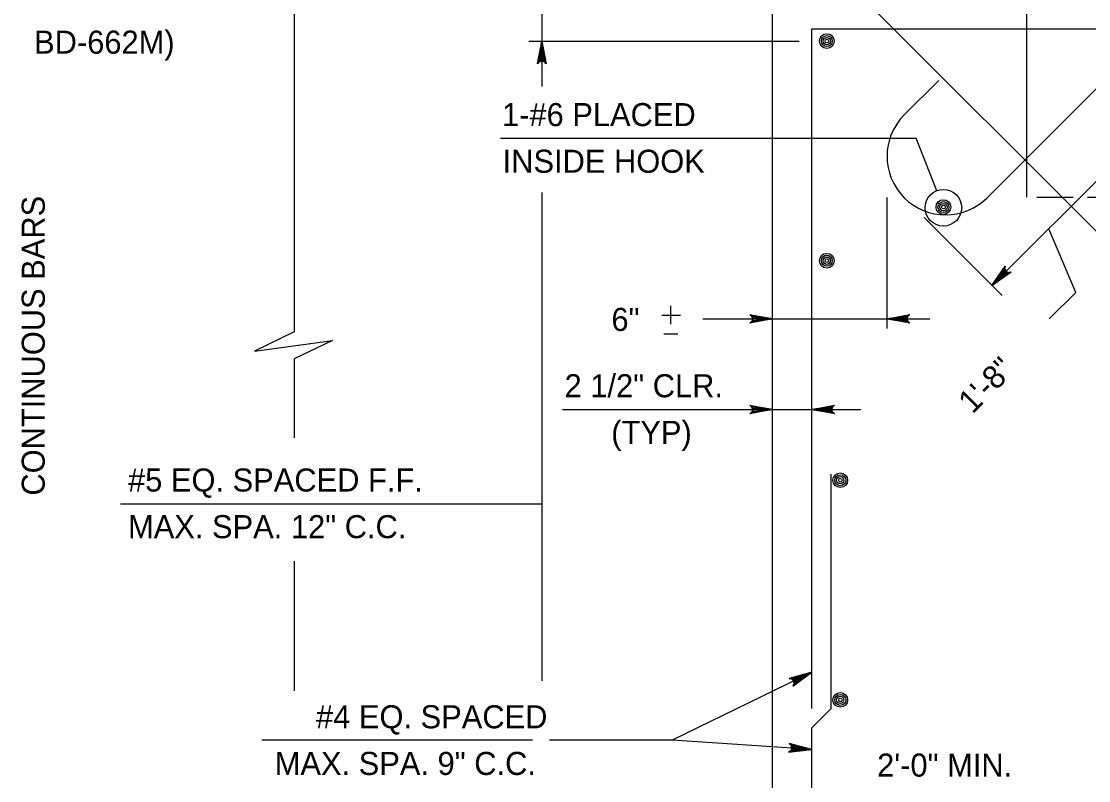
# Model space of a CAD drawing. Extents: x 638653 to 642302, y 298557 to 300414.
# Drawn here: x 640981.6 to 641120.4, y 299508.2 to 299607.1 of the extents above; entities that cross this region are included whole.
import ezdxf

# ---------------------------------------------------------------- set-up
doc = ezdxf.new("R2010")
doc.units = 0
doc.layers.add('1', color=7, linetype='Continuous')

msp = doc.modelspace()

# ---------------------------------------------------------------- linework, layer by layer
at = {"layer": '1'}
for p, q in [((641112.31, 299652.17), (641112.31, 299584.17)), ((641122.87, 299578.25), (641050.25, 299650.88)), ((641107.18, 299584.11), (641170.1, 299647.04)), ((641017.07, 299625.1), (641017.07, 299566.64)), ((641049.26, 299619.32), (641049.26, 299598.56)), ((641079.29, 299456.51), (641079.29, 299614.65)), ((641143.74, 299608.61), (641107.82, 299572.69)), ((641084.37, 299606.09), (641135.17, 299606.09)), ((641084.37, 299517.65), (641084.37, 299606.09)), ((641047.6, 299604.49), (641082.74, 299604.49)), ((641096.4, 299594.89), (641100.89, 299599.38)), ((641043.89, 299591.85), (641097.94, 299591.85)), ((641100.65, 299585.02), (641097.94, 299591.85)), ((641049.26, 299584.8), (641049.26, 299521.22)), ((641094.17, 299567.07), (641094.17, 299584.13)), ((641113.64, 299584.17), (641118.38, 299584.17)), ((641120.24, 299584.17), (641151.02, 299584.17)), ((641109.16, 299571.36), (641099, 299581.52)), ((641118.71, 299571.79), (641115.2, 299580.07)), ((641118.71, 299571.79), (641115.25, 299568.33)), ((641066.04, 299567.67), (641066.04, 299570.03)), ((641064.88, 299568.83), (641067.29, 299568.83)), ((641070.23, 299568.34), (641099.74, 299568.34)), ((641065.13, 299566.38), (641066.94, 299566.38)), ((641017.07, 299563.16), (641017.07, 299552.88)), ((641051.97, 299556.54), (641090.78, 299556.54)), ((641086.91, 299517.65), (641086.91, 299548.13)), ((640994.45, 299544.29), (641049.26, 299544.29)), ((641017.07, 299536.79), (641017.07, 299519.93)), ((641084.37, 299522.36), (641066.22, 299513.51)), ((641086.91, 299517.65), (641084.37, 299515.11)), ((641084.37, 299459.68), (641084.37, 299515.11)), ((641048.06, 299513.51), (641012.87, 299513.51)), ((641066.22, 299513.51), (641050.26, 299513.51)), ((641084.37, 299512.31), (641066.22, 299513.51))]:
    msp.add_line(p, q, dxfattribs=at)
for points in [[(641049.26, 299604.49), (641049.82, 299601.51), (641049.74, 299601.62), (641049.66, 299601.74), (641049.56, 299601.79), (641049.46, 299601.85), (641049.36, 299601.87), (641049.26, 299601.89), (641049.16, 299601.87), (641049.06, 299601.85), (641048.96, 299601.79), (641048.86, 299601.74), (641048.78, 299601.62), (641048.7, 299601.51), (641049.26, 299604.49), (641048.78, 299601.62), (641048.86, 299601.74), (641049.26, 299604.49), (641048.96, 299601.79), (641049.06, 299601.85), (641049.26, 299604.49), (641049.16, 299601.87), (641049.26, 299601.89), (641049.26, 299604.49), (641049.36, 299601.87), (641049.46, 299601.85), (641049.26, 299604.49), (641049.56, 299601.79), (641049.66, 299601.74), (641049.26, 299604.49), (641049.74, 299601.62)], [(641107.82, 299572.69), (641109.54, 299575.2), (641109.51, 299575.06), (641109.49, 299574.92), (641109.51, 299574.81), (641109.54, 299574.7), (641109.6, 299574.61), (641109.66, 299574.53), (641109.74, 299574.47), (641109.83, 299574.41), (641109.94, 299574.38), (641110.05, 299574.36), (641110.19, 299574.38), (641110.33, 299574.41), (641107.82, 299572.69), (641110.19, 299574.38), (641110.05, 299574.36), (641107.82, 299572.69), (641109.94, 299574.38), (641109.83, 299574.41), (641107.82, 299572.69), (641109.74, 299574.47), (641109.66, 299574.53), (641107.82, 299572.69), (641109.6, 299574.61), (641109.54, 299574.7), (641107.82, 299572.69), (641109.51, 299574.81), (641109.49, 299574.92), (641107.82, 299572.69), (641109.51, 299575.06)], [(641079.29, 299568.34), (641076.31, 299567.78), (641076.42, 299567.86), (641076.54, 299567.94), (641076.6, 299568.04), (641076.66, 299568.14), (641076.67, 299568.24), (641076.69, 299568.34), (641076.67, 299568.44), (641076.66, 299568.54), (641076.6, 299568.64), (641076.54, 299568.74), (641076.42, 299568.82), (641076.31, 299568.9), (641079.29, 299568.34), (641076.42, 299568.82), (641076.54, 299568.74), (641079.29, 299568.34), (641076.6, 299568.64), (641076.66, 299568.54), (641079.29, 299568.34), (641076.67, 299568.44), (641076.69, 299568.34), (641079.29, 299568.34), (641076.67, 299568.24), (641076.66, 299568.14), (641079.29, 299568.34), (641076.6, 299568.04), (641076.54, 299567.94), (641079.29, 299568.34), (641076.42, 299567.86)], [(641094.17, 299568.34), (641097.15, 299568.9), (641097.04, 299568.82), (641096.92, 299568.74), (641096.87, 299568.64), (641096.81, 299568.54), (641096.79, 299568.44), (641096.77, 299568.34), (641096.79, 299568.24), (641096.81, 299568.14), (641096.87, 299568.04), (641096.92, 299567.94), (641097.04, 299567.86), (641097.15, 299567.78), (641094.17, 299568.34), (641097.04, 299567.86), (641096.92, 299567.94), (641094.17, 299568.34), (641096.87, 299568.04), (641096.81, 299568.14), (641094.17, 299568.34), (641096.79, 299568.24), (641096.77, 299568.34), (641094.17, 299568.34), (641096.79, 299568.44), (641096.81, 299568.54), (641094.17, 299568.34), (641096.87, 299568.64), (641096.92, 299568.74), (641094.17, 299568.34), (641097.04, 299568.82)], [(641017.07, 299566.67), (641011.88, 299564.14), (641022.03, 299565.52), (641017.07, 299563.16)], [(641079.29, 299556.54), (641076.31, 299555.98), (641076.42, 299556.06), (641076.54, 299556.14), (641076.6, 299556.24), (641076.66, 299556.34), (641076.67, 299556.44), (641076.69, 299556.54), (641076.67, 299556.64), (641076.66, 299556.74), (641076.6, 299556.84), (641076.54, 299556.94), (641076.42, 299557.02), (641076.31, 299557.1), (641079.29, 299556.54), (641076.42, 299557.02), (641076.54, 299556.94), (641079.29, 299556.54), (641076.6, 299556.84), (641076.66, 299556.74), (641079.29, 299556.54), (641076.67, 299556.64), (641076.69, 299556.54), (641079.29, 299556.54), (641076.67, 299556.44), (641076.66, 299556.34), (641079.29, 299556.54), (641076.6, 299556.24), (641076.54, 299556.14), (641079.29, 299556.54), (641076.42, 299556.06)], [(641084.37, 299556.54), (641087.35, 299557.1), (641087.24, 299557.02), (641087.12, 299556.94), (641087.06, 299556.84), (641087, 299556.74), (641086.98, 299556.64), (641086.97, 299556.54), (641086.98, 299556.44), (641087, 299556.34), (641087.06, 299556.24), (641087.12, 299556.14), (641087.24, 299556.06), (641087.35, 299555.98), (641084.37, 299556.54), (641087.24, 299556.06), (641087.12, 299556.14), (641084.37, 299556.54), (641087.06, 299556.24), (641087, 299556.34), (641084.37, 299556.54), (641086.98, 299556.44), (641086.97, 299556.54), (641084.37, 299556.54), (641086.98, 299556.64), (641087, 299556.74), (641084.37, 299556.54), (641087.06, 299556.84), (641087.12, 299556.94), (641084.37, 299556.54), (641087.24, 299557.02)], [(641084.37, 299522.36), (641081.44, 299521.55), (641081.58, 299521.53), (641081.72, 299521.51), (641081.81, 299521.45), (641081.91, 299521.38), (641081.97, 299521.3), (641082.03, 299521.22), (641082.06, 299521.12), (641082.09, 299521.02), (641082.08, 299520.91), (641082.07, 299520.79), (641082, 299520.67), (641081.93, 299520.55), (641084.37, 299522.36), (641082, 299520.67), (641082.07, 299520.79), (641084.37, 299522.36), (641082.08, 299520.91), (641082.09, 299521.02), (641084.37, 299522.36), (641082.06, 299521.12), (641082.03, 299521.22), (641084.37, 299522.36), (641081.97, 299521.3), (641081.91, 299521.38), (641084.37, 299522.36), (641081.81, 299521.45), (641081.72, 299521.51), (641084.37, 299522.36), (641081.58, 299521.53)], [(641084.37, 299512.31), (641081.43, 299513.09), (641081.54, 299513), (641081.65, 299512.91), (641081.7, 299512.81), (641081.75, 299512.7), (641081.76, 299512.6), (641081.77, 299512.5), (641081.75, 299512.4), (641081.73, 299512.3), (641081.66, 299512.21), (641081.59, 299512.11), (641081.47, 299512.04), (641081.35, 299511.97), (641084.37, 299512.31), (641081.47, 299512.04), (641081.59, 299512.11), (641084.37, 299512.31), (641081.66, 299512.21), (641081.73, 299512.3), (641084.37, 299512.31), (641081.75, 299512.4), (641081.77, 299512.5), (641084.37, 299512.31), (641081.76, 299512.6), (641081.75, 299512.7), (641084.37, 299512.31), (641081.7, 299512.81), (641081.65, 299512.91), (641084.37, 299512.31), (641081.54, 299513)]]:
    msp.add_lwpolyline(points, dxfattribs=at)
for centre, radius in [((641086.34, 299604.49), 0.952), ((641086.34, 299604.49), 0.714), ((641086.34, 299604.49), 0.476), ((641086.34, 299604.49), 0.238), ((641101.5, 299582.8), 2.38), ((641101.5, 299582.89), 0.952), ((641101.5, 299582.89), 0.714), ((641101.5, 299582.89), 0.476), ((641101.5, 299582.89), 0.238), ((641086.34, 299575.91), 0.952), ((641086.34, 299575.91), 0.714), ((641086.34, 299575.91), 0.476), ((641086.34, 299575.91), 0.238), ((641088.09, 299547.34), 0.952), ((641088.09, 299547.34), 0.714), ((641088.09, 299547.34), 0.476), ((641088.09, 299547.34), 0.238), ((641088.09, 299518.76), 0.952), ((641088.09, 299518.76), 0.714), ((641088.09, 299518.76), 0.476), ((641088.09, 299518.76), 0.238)]:
    msp.add_circle(centre, radius, dxfattribs=at)
msp.add_arc((641101.79, 299589.5), 7.62, 135, 315, dxfattribs=at)

# ---------------------------------------------------------------- texts
for s, p in [('BD-662M)', (640983.23, 299602.85)), ('1-#6 PLACED', (641044.09, 299593.42)), ('INSIDE HOOK', (641044.17, 299587.35)), ('6"', (641058.32, 299566.77)), ('2 1/2" CLR.', (641052.23, 299558.14)), ('(TYP)', (641058.3, 299552.07)), ('#5 EQ. SPACED F.F.', (640995.45, 299545.87)), ('MAX. SPA. 12" C.C.', (640995.45, 299539.8)), ('#4 EQ. SPACED', (641019.9, 299515.06)), ('MAX. SPA. 9" C.C.', (641014.53, 299508.99)), ('2\'-0" MIN.', (641092.88, 299508.77))]:
    msp.add_text(s, height=3, dxfattribs=at).set_placement(p)
for s, rotation, p in [('CONTINUOUS BARS', 90, (640984.62, 299545.34)), ('1\'-8"', 45, (641105.27, 299555.88))]:
    msp.add_text(s, height=3, rotation=rotation, dxfattribs=at).set_placement(p)

doc.saveas('drawing.dxf')
